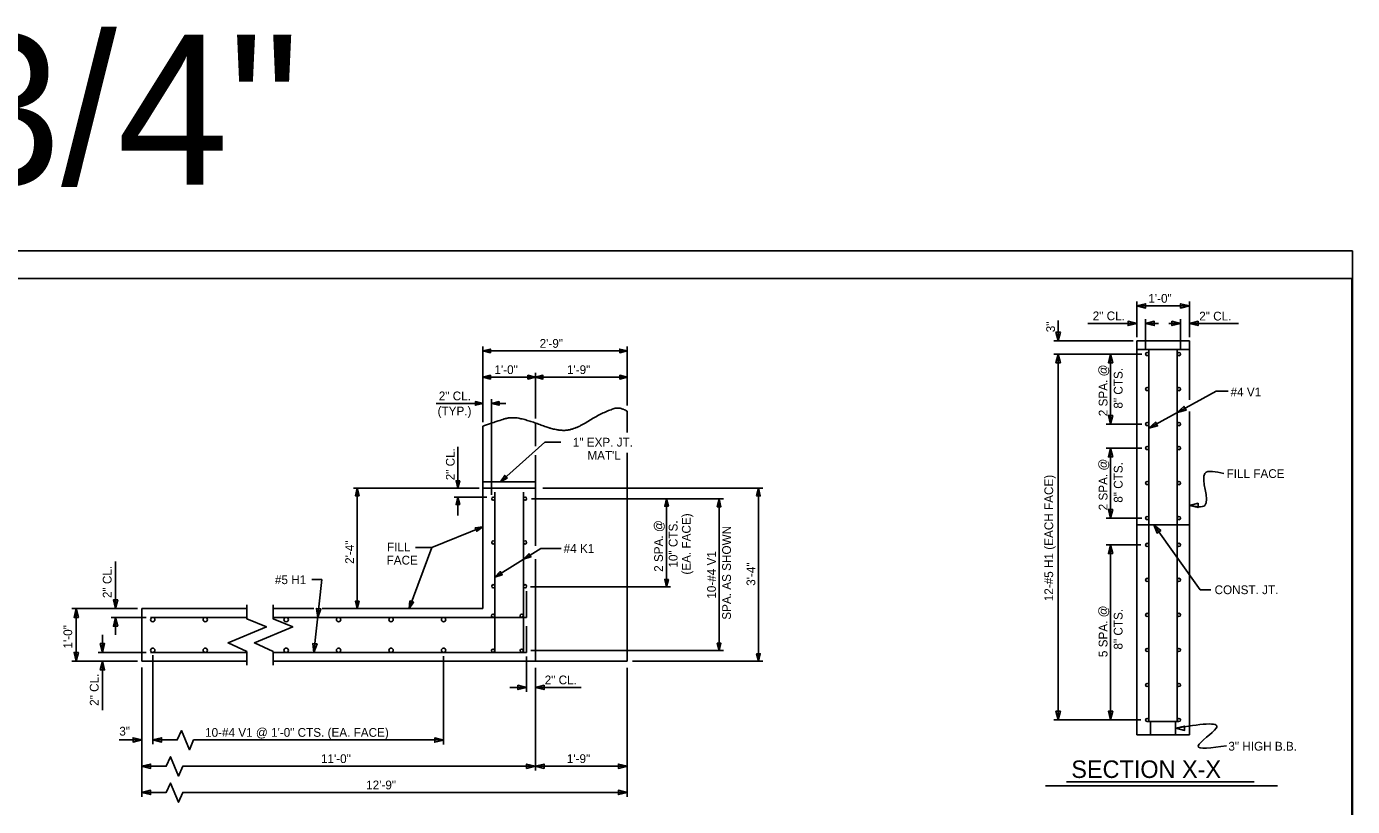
# Model space of a CAD drawing. Extents: x -41 to 251, y -169 to 237.
# Drawn here: x 18.71 to 43.97, y -80.23 to -65.38 of the extents above; entities that cross this region are included whole.
import ezdxf

# ---------------------------------------------------------------- set-up
doc = ezdxf.new("R2010")
doc.units = 0
for name, color, linetype in [('Arrowhead Terminators CELL', 7, 'Continuous'), ('Default', 7, 'Continuous'), ('Dimension Lines', 7, 'Continuous'), ('Mis Object Lines', 7, 'Continuous'), ('Mis Object Lines Hidden', 7, 'Continuous'), ('Plan Sheet CELL', 7, 'Continuous'), ('Plot Shape CELL', 7, 'Continuous'), ('Rebar K Bar Lines', 7, 'Continuous'), ('Rebar Lines', 7, 'Continuous'), ('Sub End Bent Cap Lines CELL', 7, 'Continuous'), ('Text', 7, 'Continuous'), ('Title Text', 7, 'Continuous'), ('User Information Notes CELL', 7, 'Continuous')]:
    doc.layers.add(name, color=color, linetype=linetype)

# ---------------------------------------------------------------- blocks, each defined once
blk = doc.blocks.new('AH')
at = {"layer": 'Sub End Bent Cap Lines CELL'}
blk.add_lwpolyline([(0, 0), (-1.25, 0.31), (-1.25, -0.31)], close=True, dxfattribs=at)

msp = doc.modelspace()

# ---------------------------------------------------------------- linework, layer by layer
at = {"layer": 'Arrowhead Terminators CELL'}
for points in [[(39.865, -70.696), (40.031, -70.738), (40.031, -70.655)], [(40.865, -70.696), (40.699, -70.655), (40.699, -70.738)], [(39.865, -71.031), (39.699, -70.989), (39.699, -71.072)], [(40.032, -71.031), (40.198, -71.072), (40.198, -70.989)], [(40.699, -71.029), (40.532, -70.988), (40.532, -71.071)], [(40.865, -71.029), (41.031, -71.071), (41.031, -70.988)], [(38.365, -71.363), (38.407, -71.196), (38.324, -71.196)], [(27.404, -71.553), (27.546, -71.589), (27.546, -71.518)], [(30.154, -71.553), (30.011, -71.589), (30.011, -71.518)], [(38.365, -71.613), (38.324, -71.779), (38.407, -71.779)], [(39.365, -71.613), (39.324, -71.779), (39.407, -71.779)], [(27.404, -72.053), (27.546, -72.018), (27.546, -72.089)], [(28.404, -72.053), (28.261, -72.089), (28.261, -72.018)], [(28.404, -72.053), (28.546, -72.089), (28.546, -72.018)], [(30.154, -72.053), (30.011, -72.018), (30.011, -72.089)], [(27.404, -72.553), (27.261, -72.589), (27.261, -72.518)], [(27.57, -72.553), (27.713, -72.518), (27.713, -72.589)], [(40.636, -72.727), (40.802, -72.684), (40.762, -72.611)], [(39.365, -72.946), (39.407, -72.78), (39.324, -72.78)], [(40.095, -73.026), (40.26, -72.982), (40.22, -72.909)], [(39.365, -73.404), (39.324, -73.571), (39.407, -73.571)], [(26.926, -74.169), (26.891, -74.027), (26.962, -74.027)], [(27.737, -74.044), (27.867, -73.976), (27.82, -73.923)], [(25.009, -74.169), (25.045, -74.312), (24.974, -74.312)], [(32.654, -74.17), (32.689, -74.313), (32.618, -74.313)], [(26.926, -74.337), (26.962, -74.48), (26.891, -74.48)], [(30.904, -74.367), (30.939, -74.51), (30.868, -74.51)], [(31.904, -74.379), (31.939, -74.522), (31.868, -74.522)], [(40.865, -74.494), (41.031, -74.536), (41.031, -74.453)], [(39.365, -74.738), (39.407, -74.571), (39.324, -74.571)], [(27.404, -74.901), (27.285, -74.987), (27.258, -74.921)], [(40.189, -74.863), (40.251, -75.022), (40.319, -74.974)], [(39.365, -75.248), (39.324, -75.414), (39.407, -75.414)], [(28.177, -75.521), (28.279, -75.416), (28.317, -75.476)], [(27.633, -75.859), (27.735, -75.754), (27.773, -75.814)], [(30.904, -76.046), (30.868, -75.903), (30.939, -75.903)], [(24.255, -76.628), (24.315, -76.467), (24.232, -76.458)], [(25.009, -76.461), (24.974, -76.319), (25.045, -76.319)], [(25.998, -76.461), (26.014, -76.315), (26.081, -76.34)], [(24.183, -77.294), (24.242, -77.134), (24.16, -77.125)], [(31.904, -77.261), (31.868, -77.119), (31.939, -77.119)], [(32.654, -77.462), (32.618, -77.319), (32.689, -77.319)], [(28.237, -77.961), (28.071, -77.92), (28.071, -78.003)], [(28.404, -77.961), (28.57, -78.003), (28.57, -77.92)], [(38.365, -78.581), (38.407, -78.415), (38.324, -78.415)], [(39.365, -78.581), (39.407, -78.415), (39.324, -78.415)], [(40.609, -78.739), (40.775, -78.78), (40.775, -78.697)], [(20.904, -78.961), (20.737, -78.92), (20.737, -79.003)], [(21.112, -78.961), (21.279, -79.003), (21.279, -78.92)], [(26.654, -78.963), (26.487, -79.004), (26.487, -78.921)], [(20.904, -79.461), (21.07, -79.503), (21.07, -79.42)], [(28.402, -79.461), (28.236, -79.42), (28.236, -79.503)], [(28.402, -79.461), (28.568, -79.503), (28.568, -79.42)], [(30.152, -79.461), (29.986, -79.42), (29.986, -79.503)], [(20.904, -79.961), (21.07, -80.003), (21.07, -79.92)], [(30.152, -79.961), (29.986, -79.92), (29.986, -80.003)]]:
    msp.add_lwpolyline(points, close=True, dxfattribs=at)
at = {"layer": 'Default'}
for points in [[(22.904, -77.536), (22.904, -77.278), (22.546, -77.114), (23.279, -76.808), (22.904, -76.653), (22.904, -76.391)], [(23.406, -77.536), (23.406, -77.278), (23.048, -77.114), (23.781, -76.808), (23.406, -76.653), (23.406, -76.391)], [(21.449, -78.961), (21.578, -78.961), (21.66, -78.782), (21.813, -79.149), (21.891, -78.961), (22.022, -78.961)], [(21.241, -79.461), (21.37, -79.461), (21.452, -79.282), (21.605, -79.649), (21.682, -79.461), (21.813, -79.461)], [(21.241, -79.961), (21.37, -79.961), (21.452, -79.782), (21.605, -80.149), (21.682, -79.961), (21.813, -79.961)]]:
    msp.add_lwpolyline(points, dxfattribs=at)
at = {"layer": 'Dimension Lines'}
for p, q in [((39.865, -71.291), (39.865, -70.613)), ((40.865, -70.696), (39.865, -70.696)), ((40.865, -71.291), (40.865, -70.613)), ((38.365, -71.363), (38.365, -70.975)), ((40.032, -71.541), (40.032, -70.947)), ((40.699, -71.541), (40.699, -70.946)), ((39.865, -71.031), (38.928, -71.031)), ((40.032, -71.031), (40.278, -71.031)), ((40.699, -71.029), (40.476, -71.029)), ((41.802, -71.029), (40.865, -71.029)), ((39.793, -71.363), (38.282, -71.363)), ((39.961, -71.613), (38.282, -71.613)), ((38.365, -71.613), (38.365, -78.581)), ((39.365, -71.613), (39.365, -72.946)), ((40.095, -73.026), (41.379, -72.318)), ((41.379, -72.318), (41.605, -72.318)), ((39.961, -72.946), (39.282, -72.946)), ((26.926, -74.169), (26.926, -73.382)), ((28.584, -73.288), (27.737, -74.044)), ((28.886, -73.288), (28.584, -73.288)), ((39.961, -73.404), (39.282, -73.404)), ((39.365, -73.404), (39.365, -74.738)), ((27.332, -74.169), (24.937, -74.169)), ((25.009, -74.169), (25.009, -76.461)), ((28.405, -74.044), (28.07, -74.044)), ((28.404, -74.169), (28.405, -74.044)), ((28.544, -74.169), (32.738, -74.169)), ((32.654, -77.461), (32.654, -74.169)), ((27.48, -74.337), (26.854, -74.337)), ((26.926, -74.337), (26.926, -74.687)), ((28.331, -74.367), (31.988, -74.367)), ((30.904, -74.367), (30.904, -76.046)), ((31.904, -74.367), (31.904, -77.261)), ((39.961, -74.738), (39.282, -74.738)), ((27.404, -74.901), (26.433, -75.294)), ((40.189, -74.863), (41.071, -76.103)), ((26.433, -75.294), (25.998, -76.461)), ((26.433, -75.294), (26.118, -75.294)), ((39.941, -75.248), (39.282, -75.248)), ((39.365, -78.581), (39.365, -75.248)), ((20.404, -75.562), (20.404, -76.461)), ((28.309, -76.046), (30.977, -76.046)), ((41.071, -76.103), (41.275, -76.103)), ((20.82, -76.461), (19.57, -76.461)), ((19.654, -76.461), (19.654, -77.461)), ((20.82, -76.461), (20.467, -76.461)), ((20.987, -76.628), (20.32, -76.628)), ((20.404, -76.962), (20.404, -76.628)), ((20.154, -76.96), (20.154, -77.294)), ((20.987, -77.294), (20.07, -77.294)), ((28.316, -77.261), (31.988, -77.261)), ((20.82, -77.461), (19.57, -77.461)), ((20.154, -78.394), (20.154, -77.461)), ((20.82, -77.461), (20.178, -77.461)), ((21.112, -77.347), (21.112, -79.044)), ((26.654, -79.046), (26.654, -77.365)), ((28.237, -77.37), (28.237, -78.044)), ((30.254, -77.461), (32.738, -77.461)), ((20.904, -77.589), (20.904, -79.149)), ((20.905, -77.58), (20.905, -80.044)), ((28.404, -77.589), (28.404, -79.544)), ((30.154, -77.589), (30.154, -80.044)), ((28.237, -77.961), (27.918, -77.961)), ((28.404, -77.961), (29.278, -77.961)), ((39.941, -78.581), (38.282, -78.581)), ((20.475, -78.961), (20.904, -78.961)), ((21.449, -78.961), (21.112, -78.961)), ((22.022, -78.961), (26.654, -78.961)), ((21.241, -79.461), (20.904, -79.461)), ((28.402, -79.461), (21.815, -79.461)), ((30.152, -79.461), (28.404, -79.461)), ((21.241, -79.961), (20.904, -79.961)), ((30.154, -79.961), (21.815, -79.961))]:
    msp.add_line(p, q, dxfattribs=at)
for points in [[(28.07, -74.044), (27.404, -74.044), (27.404, -74.169), (28.404, -74.169)], [(27.633, -75.859), (28.51, -75.314), (28.892, -75.314)], [(24.183, -77.294), (24.333, -75.908), (24.141, -75.908)]]:
    msp.add_lwpolyline(points, dxfattribs=at)
for points in [[(40.865, -74.494), (41.162, -74.494), (41.162, -73.885), (41.521, -73.885)], [(40.609, -78.739), (41.375, -78.739), (41.036, -79.071), (41.573, -79.071)]]:
    msp.add_spline(points, degree=3, dxfattribs=at)
at = {"layer": 'Mis Object Lines'}
for p, q in [((39.865, -78.863), (39.865, -71.363)), ((39.865, -71.363), (40.865, -71.363)), ((40.865, -72.484), (40.865, -71.363)), ((30.154, -73.106), (30.154, -72.701)), ((40.865, -78.863), (40.865, -72.71)), ((27.404, -76.461), (27.404, -72.984)), ((28.404, -73.369), (28.404, -72.925)), ((30.154, -77.461), (30.154, -73.497)), ((28.404, -75.265), (28.404, -73.536)), ((27.404, -74.169), (28.404, -74.169)), ((28.404, -77.461), (28.404, -75.517)), ((20.904, -76.461), (22.904, -76.461)), ((24.179, -76.461), (23.406, -76.461)), ((27.404, -76.461), (24.34, -76.461)), ((22.904, -77.461), (20.904, -77.461)), ((28.404, -77.461), (23.406, -77.461)), ((28.404, -77.461), (30.154, -77.461)), ((40.865, -78.863), (39.865, -78.863))]:
    msp.add_line(p, q, dxfattribs=at)
msp.add_lwpolyline([(20.904, -76.461), (20.904, -77.461)], dxfattribs=at)
msp.add_open_spline([(27.404, -72.984), (27.535, -72.94), (27.667, -72.896), (27.798, -72.853), (27.821, -72.845), (27.844, -72.84), (27.867, -72.835), (27.891, -72.83), (27.914, -72.828), (27.937, -72.827), (27.984, -72.824), (28.032, -72.825), (28.079, -72.834), (28.177, -72.854), (28.272, -72.882), (28.366, -72.913), (28.464, -72.945), (28.558, -72.984), (28.656, -73.015), (28.703, -73.03), (28.751, -73.042), (28.8, -73.051), (28.835, -73.058), (28.871, -73.063), (28.907, -73.065), (28.919, -73.066), (28.931, -73.067), (28.943, -73.067), (28.956, -73.067), (28.969, -73.066), (28.982, -73.065), (28.995, -73.064), (29.008, -73.063), (29.021, -73.061), (29.047, -73.056), (29.073, -73.05), (29.099, -73.042), (29.153, -73.026), (29.206, -73.004), (29.256, -72.979), (29.365, -72.924), (29.464, -72.857), (29.571, -72.799), (29.669, -72.746), (29.77, -72.7), (29.874, -72.662), (29.941, -72.638), (30.02, -72.641), (30.087, -72.668), (30.11, -72.677), (30.133, -72.688), (30.154, -72.701)], degree=3, dxfattribs=at)
at = {"layer": 'Mis Object Lines Hidden'}
msp.add_line((40.865, -74.863), (39.865, -74.863), dxfattribs=at)
at = {"layer": 'Plan Sheet CELL'}
for p, q in [((43.974, -69.65), (43.974, -69.65)), ((1.402, -70.174), (43.962, -70.174)), ((43.962, -70.174), (43.962, -98.104))]:
    msp.add_line(p, q, dxfattribs=at)
at = {"layer": 'Plot Shape CELL'}
msp.add_lwpolyline([(0, -69.65), (43.974, -69.65), (43.974, -98.91), (0, -98.91)], close=True, dxfattribs=at)
at = {"layer": 'Rebar K Bar Lines'}
for p, q in [((27.633, -77.294), (27.633, -74.243)), ((28.175, -77.294), (28.175, -74.243))]:
    msp.add_line(p, q, dxfattribs=at)
at = {"layer": 'Rebar Lines'}
for p, q in [((40.095, -78.612), (40.095, -71.529)), ((40.636, -78.612), (40.636, -71.529)), ((28.237, -76.628), (28.237, -76.128)), ((21.072, -76.628), (22.904, -76.628)), ((23.406, -76.628), (28.237, -76.628)), ((28.237, -77.294), (28.237, -76.794)), ((21.072, -77.294), (22.904, -77.294)), ((23.406, -77.294), (28.237, -77.294)), ((40.667, -78.612), (40.063, -78.612)), ((40.127, -78.612), (40.127, -78.862)), ((40.602, -78.612), (40.602, -78.862))]:
    msp.add_line(p, q, dxfattribs=at)
for centre, radius in [((27.602, -74.367), 0.0312), ((28.206, -74.367), 0.0312), ((27.602, -75.201), 0.0312), ((28.206, -75.201), 0.0312), ((27.602, -76.034), 0.0312), ((28.206, -76.034), 0.0312), ((21.112, -76.669), 0.0417), ((22.112, -76.669), 0.0417), ((23.654, -76.669), 0.0417), ((24.654, -76.669), 0.0417), ((25.654, -76.669), 0.0417), ((26.654, -76.669), 0.0417), ((27.598, -76.596), 0.0312), ((28.142, -76.596), 0.0312), ((21.112, -77.253), 0.0417), ((22.112, -77.253), 0.0417), ((23.654, -77.253), 0.0417), ((24.654, -77.253), 0.0417), ((25.654, -77.253), 0.0417), ((26.654, -77.253), 0.0417), ((27.598, -77.261), 0.0312), ((28.142, -77.261), 0.0312)]:
    msp.add_circle(centre, radius, dxfattribs=at)
for centre in [(40.063, -71.613), (40.667, -71.613), (40.063, -72.279), (40.667, -72.279), (40.063, -72.946), (40.667, -72.946), (40.063, -73.404), (40.667, -73.404), (40.063, -74.071), (40.667, -74.071), (40.063, -74.738), (40.667, -74.738), (40.063, -75.248), (40.667, -75.248), (40.063, -75.915), (40.667, -75.915), (40.063, -76.581), (40.667, -76.581), (40.063, -77.248), (40.667, -77.248), (40.063, -77.915), (40.667, -77.915), (40.063, -78.581), (40.667, -78.581)]:
    msp.add_ellipse(centre, major_axis=(0, -0.0313), ratio=0.99999, dxfattribs=at)
at = {"layer": 'Text'}
for p, q in [((27.404, -72.912), (27.404, -71.47)), ((30.154, -72.591), (30.154, -71.47)), ((27.404, -71.553), (30.154, -71.553)), ((28.404, -72.838), (28.404, -71.97)), ((28.404, -72.053), (27.404, -72.053)), ((28.404, -72.053), (30.154, -72.053)), ((27.57, -74.295), (27.57, -72.47)), ((27.404, -72.553), (26.511, -72.553)), ((27.57, -72.553), (27.841, -72.553))]:
    msp.add_line(p, q, dxfattribs=at)
at = {"layer": 'Title Text'}
for p, q in [((38.123, -79.834), (42.545, -79.834)), ((38.526, -79.761), (42.1, -79.761))]:
    msp.add_line(p, q, dxfattribs=at)
at = {"layer": 'User Information Notes CELL'}
msp.add_line((39.865, -71.529), (40.865, -71.529), dxfattribs=at)

# ---------------------------------------------------------------- block references
at = {"layer": 'Arrowhead Terminators CELL', "xscale": 0.1336, "yscale": -0.1336}
for p, rotation in [((20.404, -76.461), -90), ((19.654, -76.461), 90), ((20.404, -76.628), 90), ((19.654, -77.461), -90), ((20.154, -77.294), -90), ((20.154, -77.461), 90)]:
    msp.add_blockref('AH', p, dxfattribs=dict(at, rotation=rotation))

# ---------------------------------------------------------------- texts
at = {"layer": 'Text'}
for s, height, p in [('SCALE = 3/4"', 2.86, (0.339, -68.389)), ('2\'-9"', 0.167, (28.485, -71.494)), ('1\'-9"', 0.167, (29.005, -71.994)), ('1" EXP. JT.', 0.167, (29.117, -73.375)), ("MAT'L", 0.167, (29.394, -73.626)), ('FILL', 0.167, (25.576, -75.37)), ('FACE', 0.167, (25.568, -75.621)), ('#5 H1', 0.167, (23.44, -75.994)), ('2" CL. ', 0.167, (28.581, -77.902)), ('3"', 0.167, (20.475, -78.878)), ('10-#4 V1 @ 1\'-0" CTS. (EA. FACE)', 0.167, (22.109, -78.901)), ('3" HIGH B.B.', 0.167, (41.609, -79.164)), ('11\'-0"', 0.167, (24.317, -79.401)), ('1\'-9"', 0.167, (29.003, -79.401)), ('12\'-9"', 0.167, (25.179, -79.902))]:
    msp.add_text(s, height=height, dxfattribs=at).set_placement(p)
for s, rotation, p in [('1\'-0"', 360, (40.084, -70.636)), ('2" CL.', 360, (39.024, -70.97)), ('2" CL.', 360, (41.054, -70.974)), ('3"', 90, (38.305, -71.198)), ('1\'-0"', 360, (27.623, -71.994)), ('2 SPA. @', 90, (39.305, -72.797)), ('8" CTS.', 90, (39.593, -72.652)), ('#4 V1', 360, (41.651, -72.418)), ('2" CL.', 360, (26.562, -72.494)), ('(TYP.)', 360, (26.54, -72.781)), ('2" CL.', 90, (26.866, -74.017)), ('2 SPA. @', 90, (39.305, -74.589)), ('8" CTS.', 90, (39.593, -74.444)), ('12-#5 H1 (EACH FACE)', 90, (38.27, -76.32)), ('FILL FACE', 360, (41.575, -73.973)), ('(EA. FACE)', 90, (31.363, -75.813)), ('2 SPA. @', 90, (30.834, -75.76)), ('10" CTS.', 90, (31.112, -75.679)), ('SPA. AS SHOWN', 90, (32.13, -76.672)), ('2\'-4"', 90, (24.947, -75.609)), ('#4 K1', 360, (28.942, -75.399)), ('10-#4 V1', 90, (31.843, -76.272)), ('2" CL.', 90, (20.327, -76.259)), ('3\'-4"', 90, (32.594, -76.026)), ('CONST. JT.', 360, (41.346, -76.185)), ('5 SPA. @', 90, (39.305, -77.384)), ('8" CTS.', 90, (39.592, -77.24)), ('1\'-0"', 90, (19.577, -77.22)), ('2" CL.', 90, (20.08, -78.312))]:
    msp.add_text(s, height=0.167, rotation=rotation, dxfattribs=at).set_placement(p)
at = {"layer": 'Title Text'}
msp.add_text('SECTION X-X', height=0.33399, dxfattribs=at).set_placement((38.616, -79.685))

doc.saveas('drawing.dxf')
